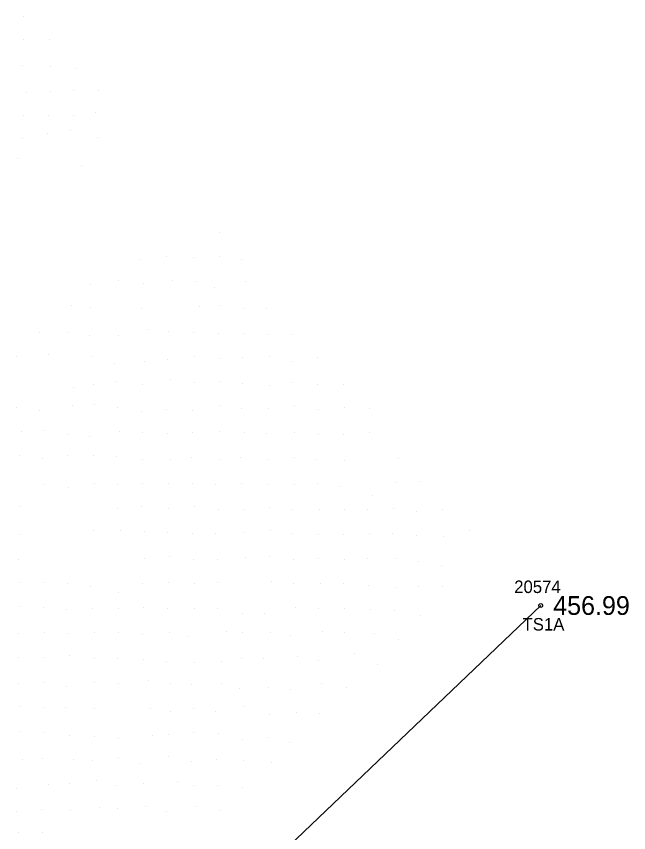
# Model space of a CAD drawing. Extents: x 1747760 to 1751131, y 649333 to 653784.
# Drawn here: x 1749292.3 to 1749341.3, y 651329.8 to 651395.1 of the extents above; entities that cross this region are included whole.
import ezdxf

# ---------------------------------------------------------------- set-up
doc = ezdxf.new("R2010")
doc.units = 0
for name, color, linetype in [('RD_DTM_BkLn2', 7, 'Continuous'), ('RD_DTM_BkLn_txCode', 7, 'Continuous'), ('RD_DTM_Spot', 7, 'Continuous'), ('RD_EX_TX_Misc_ELEV', 7, 'Continuous'), ('RD_SMD_Locator', 7, 'Continuous')]:
    doc.layers.add(name, color=color, linetype=linetype)

msp = doc.modelspace()

# ---------------------------------------------------------------- linework, layer by layer
at = {"layer": 'RD_DTM_BkLn2'}
msp.add_lwpolyline([(1749334.274, 651347.939), (1749311.737, 651326.42), (1749292.613, 651306.019), (1749271.131, 651290.935), (1749254.537, 651276.811), (1749242.73, 651265.483), (1749232.71, 651251.743), (1749211.561, 651228.743), (1749190.496, 651216.053), (1749178.766, 651203.369)], dxfattribs=at)
at = {"layer": 'RD_DTM_Spot'}
for p, q in [((1749292.882, 651395.107), (1749292.882, 651395.107)), ((1749292.871, 651393.243), (1749292.871, 651393.243)), ((1749294.951, 651393.255), (1749294.951, 651393.255)), ((1749292.804, 651391.182), (1749292.804, 651391.182)), ((1749295.066, 651391.129), (1749295.066, 651391.129)), ((1749297.111, 651390.956), (1749297.111, 651390.956)), ((1749295.032, 651389.121), (1749295.032, 651389.121)), ((1749296.894, 651389.139), (1749296.894, 651389.139)), ((1749298.853, 651389.19), (1749298.853, 651389.19)), ((1749293.146, 651389.02), (1749293.146, 651389.02)), ((1749294.871, 651387.183), (1749294.871, 651387.183)), ((1749296.905, 651387.181), (1749296.905, 651387.181)), ((1749298.636, 651387.446), (1749298.636, 651387.446)), ((1749292.929, 651387.136), (1749292.929, 651387.136)), ((1749296.614, 651385.966), (1749296.614, 651385.966)), ((1749292.834, 651385.289), (1749292.834, 651385.289)), ((1749294.792, 651385.765), (1749294.792, 651385.765)), ((1749298.822, 651385.444), (1749298.822, 651385.444)), ((1749292.409, 651383.729), (1749292.409, 651383.729)), ((1749297.559, 651383.152), (1749297.559, 651383.152)), ((1749308.556, 651377.821), (1749308.556, 651377.821)), ((1749302.269, 651375.614), (1749302.269, 651375.614)), ((1749304.349, 651375.851), (1749304.349, 651375.851)), ((1749306.491, 651375.773), (1749306.491, 651375.773)), ((1749308.577, 651375.918), (1749308.577, 651375.918)), ((1749310.36, 651375.641), (1749310.36, 651375.641)), ((1749298.265, 651373.62), (1749298.265, 651373.62)), ((1749300.482, 651373.943), (1749300.482, 651373.943)), ((1749302.484, 651373.705), (1749302.484, 651373.705)), ((1749304.836, 651373.967), (1749304.836, 651373.967)), ((1749306.685, 651373.866), (1749306.685, 651373.866)), ((1749310.682, 651373.857), (1749310.682, 651373.857)), ((1749308.135, 651373.399), (1749308.135, 651373.399)), ((1749296.695, 651371.959), (1749296.695, 651371.959)), ((1749298.221, 651371.814), (1749298.221, 651371.814)), ((1749302.3, 651371.74), (1749302.3, 651371.74)), ((1749306.954, 651371.839), (1749306.954, 651371.839)), ((1749308.684, 651371.929), (1749308.684, 651371.929)), ((1749310.533, 651371.69), (1749310.533, 651371.69)), ((1749312.349, 651371.712), (1749312.349, 651371.712)), ((1749294.175, 651369.759), (1749294.175, 651369.759)), ((1749296.531, 651369.819), (1749296.531, 651369.819)), ((1749298.199, 651369.54), (1749298.199, 651369.54)), ((1749300.531, 651369.538), (1749300.531, 651369.538)), ((1749302.887, 651370), (1749302.887, 651370)), ((1749304.53, 651369.914), (1749304.53, 651369.914)), ((1749306.509, 651369.8), (1749306.509, 651369.8)), ((1749308.491, 651369.676), (1749308.491, 651369.676)), ((1749310.613, 651369.743), (1749310.613, 651369.743)), ((1749312.447, 651369.667), (1749312.447, 651369.667)), ((1749314.344, 651369.627), (1749314.344, 651369.627)), ((1749292.357, 651367.857), (1749292.357, 651367.857)), ((1749294.865, 651368.072), (1749294.865, 651368.072)), ((1749298.312, 651367.905), (1749298.312, 651367.905)), ((1749304.437, 651367.665), (1749304.437, 651367.665)), ((1749306.601, 651367.88), (1749306.601, 651367.88)), ((1749308.597, 651367.748), (1749308.597, 651367.748)), ((1749310.394, 651367.757), (1749310.394, 651367.757)), ((1749312.568, 651367.875), (1749312.568, 651367.875)), ((1749316.383, 651367.812), (1749316.383, 651367.812)), ((1749300.178, 651367.287), (1749300.178, 651367.287)), ((1749302.541, 651367.452), (1749302.541, 651367.452)), ((1749314.421, 651367.479), (1749314.421, 651367.479)), ((1749298.524, 651365.64), (1749298.524, 651365.64)), ((1749300.362, 651365.892), (1749300.362, 651365.892)), ((1749302.419, 651365.603), (1749302.419, 651365.603)), ((1749304.641, 651366.002), (1749304.641, 651366.002)), ((1749306.544, 651365.808), (1749306.544, 651365.808)), ((1749308.562, 651365.852), (1749308.562, 651365.852)), ((1749310.432, 651365.677), (1749310.432, 651365.677)), ((1749314.428, 651365.778), (1749314.428, 651365.778)), ((1749316.398, 651365.633), (1749316.398, 651365.633)), ((1749318.517, 651365.64), (1749318.517, 651365.64)), ((1749296.915, 651365.374), (1749296.915, 651365.374)), ((1749312.546, 651365.515), (1749312.546, 651365.515)), ((1749292.335, 651363.805), (1749292.335, 651363.805)), ((1749296.806, 651363.959), (1749296.806, 651363.959)), ((1749298.558, 651364.004), (1749298.558, 651364.004)), ((1749300.374, 651363.804), (1749300.374, 651363.804)), ((1749304.318, 651363.633), (1749304.318, 651363.633)), ((1749308.637, 651363.929), (1749308.637, 651363.929)), ((1749310.33, 651363.692), (1749310.33, 651363.692)), ((1749312.482, 651363.676), (1749312.482, 651363.676)), ((1749314.578, 651363.932), (1749314.578, 651363.932)), ((1749316.479, 651363.644), (1749316.479, 651363.644)), ((1749318.555, 651363.785), (1749318.555, 651363.785)), ((1749320.609, 651363.694), (1749320.609, 651363.694)), ((1749294.14, 651363.584), (1749294.14, 651363.584)), ((1749302.361, 651363.494), (1749302.361, 651363.494)), ((1749306.403, 651363.574), (1749306.403, 651363.574)), ((1749292.727, 651361.875), (1749292.727, 651361.875)), ((1749294.546, 651361.987), (1749294.546, 651361.987)), ((1749300.55, 651361.856), (1749300.55, 651361.856)), ((1749302.422, 651361.81), (1749302.422, 651361.81)), ((1749304.425, 651361.741), (1749304.425, 651361.741)), ((1749306.379, 651361.78), (1749306.379, 651361.78)), ((1749308.548, 651361.899), (1749308.548, 651361.899)), ((1749310.535, 651361.807), (1749310.535, 651361.807)), ((1749312.371, 651361.69), (1749312.371, 651361.69)), ((1749314.536, 651361.768), (1749314.536, 651361.768)), ((1749318.494, 651361.656), (1749318.494, 651361.656)), ((1749320.574, 651361.793), (1749320.574, 651361.793)), ((1749296.449, 651361.611), (1749296.449, 651361.611)), ((1749298.201, 651361.433), (1749298.201, 651361.433)), ((1749316.493, 651361.613), (1749316.493, 651361.613)), ((1749292.551, 651359.974), (1749292.551, 651359.974)), ((1749294.402, 651359.691), (1749294.402, 651359.691)), ((1749296.444, 651359.981), (1749296.444, 651359.981)), ((1749298.475, 651359.914), (1749298.475, 651359.914)), ((1749300.343, 651359.883), (1749300.343, 651359.883)), ((1749306.36, 651359.815), (1749306.36, 651359.815)), ((1749310.268, 651359.759), (1749310.268, 651359.759)), ((1749314.537, 651359.758), (1749314.537, 651359.758)), ((1749322.936, 651359.725), (1749322.936, 651359.725)), ((1749302.382, 651359.663), (1749302.382, 651359.663)), ((1749304.642, 651359.647), (1749304.642, 651359.647)), ((1749308.562, 651359.652), (1749308.562, 651359.652)), ((1749312.435, 651359.663), (1749312.435, 651359.663)), ((1749316.293, 651359.663), (1749316.293, 651359.663)), ((1749318.554, 651359.588), (1749318.554, 651359.588)), ((1749310.361, 651357.744), (1749310.361, 651357.744)), ((1749322.694, 651357.828), (1749322.694, 651357.828)), ((1749324.605, 651357.879), (1749324.605, 651357.879)), ((1749294.529, 651357.665), (1749294.529, 651357.665)), ((1749296.502, 651357.393), (1749296.502, 651357.393)), ((1749298.556, 651357.716), (1749298.556, 651357.716)), ((1749300.402, 651357.646), (1749300.402, 651357.646)), ((1749302.386, 651357.706), (1749302.386, 651357.706)), ((1749304.494, 651357.714), (1749304.494, 651357.714)), ((1749306.396, 651357.699), (1749306.396, 651357.699)), ((1749308.289, 651357.647), (1749308.289, 651357.647)), ((1749312.419, 651357.6), (1749312.419, 651357.6)), ((1749314.601, 651357.609), (1749314.601, 651357.609)), ((1749316.422, 651357.676), (1749316.422, 651357.676)), ((1749318.284, 651357.44), (1749318.284, 651357.44)), ((1749320.782, 651356.756), (1749320.782, 651356.756)), ((1749292.555, 651355.86), (1749292.555, 651355.86)), ((1749302.358, 651355.846), (1749302.358, 651355.846)), ((1749306.539, 651355.893), (1749306.539, 651355.893)), ((1749312.592, 651355.786), (1749312.592, 651355.786)), ((1749300.395, 651355.691), (1749300.395, 651355.691)), ((1749304.51, 651355.67), (1749304.51, 651355.67)), ((1749308.462, 651355.612), (1749308.462, 651355.612)), ((1749310.507, 651355.605), (1749310.507, 651355.605)), ((1749314.455, 651355.61), (1749314.455, 651355.61)), ((1749316.596, 651355.618), (1749316.596, 651355.618)), ((1749318.552, 651355.638), (1749318.552, 651355.638)), ((1749320.413, 651355.632), (1749320.413, 651355.632)), ((1749322.497, 651355.693), (1749322.497, 651355.693)), ((1749324.353, 651355.5), (1749324.353, 651355.5)), ((1749326.444, 651355.636), (1749326.444, 651355.636)), ((1749298.515, 651353.955), (1749298.515, 651353.955)), ((1749300.629, 651353.913), (1749300.629, 651353.913)), ((1749302.539, 651353.826), (1749302.539, 651353.826)), ((1749312.69, 651353.937), (1749312.69, 651353.937)), ((1749328.554, 651353.953), (1749328.554, 651353.953)), ((1749292.626, 651353.604), (1749292.626, 651353.604)), ((1749304.428, 651353.759), (1749304.428, 651353.759)), ((1749306.432, 651353.675), (1749306.432, 651353.675)), ((1749308.251, 651353.728), (1749308.251, 651353.728)), ((1749310.591, 651353.788), (1749310.591, 651353.788)), ((1749314.422, 651353.706), (1749314.422, 651353.706)), ((1749316.483, 651353.6), (1749316.483, 651353.6)), ((1749318.465, 651353.603), (1749318.465, 651353.603)), ((1749320.575, 651353.71), (1749320.575, 651353.71)), ((1749322.446, 651353.707), (1749322.446, 651353.707)), ((1749324.366, 651353.535), (1749324.366, 651353.535)), ((1749326.506, 651353.491), (1749326.506, 651353.491)), ((1749304.554, 651351.886), (1749304.554, 651351.886)), ((1749292.509, 651351.601), (1749292.509, 651351.601)), ((1749302.539, 651351.698), (1749302.539, 651351.698)), ((1749306.472, 651351.659), (1749306.472, 651351.659)), ((1749308.452, 651351.601), (1749308.452, 651351.601)), ((1749310.657, 651351.823), (1749310.657, 651351.823)), ((1749312.568, 651351.845), (1749312.568, 651351.845)), ((1749314.472, 651351.594), (1749314.472, 651351.594)), ((1749316.524, 651351.698), (1749316.524, 651351.698)), ((1749318.6, 651351.636), (1749318.6, 651351.636)), ((1749320.441, 651351.728), (1749320.441, 651351.728)), ((1749322.738, 651351.728), (1749322.738, 651351.728)), ((1749324.459, 651351.456), (1749324.459, 651351.456)), ((1749326.36, 651351.18), (1749326.36, 651351.18)), ((1749292.636, 651349.807), (1749292.636, 651349.807)), ((1749294.453, 651349.798), (1749294.453, 651349.798)), ((1749296.379, 651349.73), (1749296.379, 651349.73)), ((1749298.288, 651349.484), (1749298.288, 651349.484)), ((1749302.436, 651349.694), (1749302.436, 651349.694)), ((1749304.455, 651349.746), (1749304.455, 651349.746)), ((1749306.565, 651349.734), (1749306.565, 651349.734)), ((1749308.442, 651349.758), (1749308.442, 651349.758)), ((1749312.716, 651349.826), (1749312.716, 651349.826)), ((1749314.513, 651349.738), (1749314.513, 651349.738)), ((1749316.635, 651349.664), (1749316.635, 651349.664)), ((1749318.501, 651349.73), (1749318.501, 651349.73)), ((1749320.523, 651349.509), (1749320.523, 651349.509)), ((1749322.743, 651349.416), (1749322.743, 651349.416)), ((1749324.518, 651349.457), (1749324.518, 651349.457)), ((1749326.383, 651349.443), (1749326.383, 651349.443)), ((1749300.504, 651348.985), (1749300.504, 651348.985)), ((1749292.657, 651347.823), (1749292.657, 651347.823)), ((1749294.471, 651347.748), (1749294.471, 651347.748)), ((1749296.37, 651347.622), (1749296.37, 651347.622)), ((1749298.45, 651347.673), (1749298.45, 651347.673)), ((1749300.518, 651347.698), (1749300.518, 651347.698)), ((1749302.462, 651347.752), (1749302.462, 651347.752)), ((1749304.383, 651347.686), (1749304.383, 651347.686)), ((1749306.538, 651347.71), (1749306.538, 651347.71)), ((1749308.45, 651347.685), (1749308.45, 651347.685)), ((1749310.426, 651347.312), (1749310.426, 651347.312)), ((1749312.18, 651347.314), (1749312.18, 651347.314)), ((1749314.632, 651347.779), (1749314.632, 651347.779)), ((1749316.501, 651347.69), (1749316.501, 651347.69)), ((1749318.549, 651347.677), (1749318.549, 651347.677)), ((1749320.618, 651347.608), (1749320.618, 651347.608)), ((1749322.584, 651347.529), (1749322.584, 651347.529)), ((1749324.654, 651347.137), (1749324.654, 651347.137)), ((1749292.492, 651345.69), (1749292.492, 651345.69)), ((1749294.565, 651345.799), (1749294.565, 651345.799)), ((1749296.485, 651345.667), (1749296.485, 651345.667)), ((1749298.543, 651345.787), (1749298.543, 651345.787)), ((1749300.454, 651345.799), (1749300.454, 651345.799)), ((1749302.449, 651345.59), (1749302.449, 651345.59)), ((1749304.609, 651345.744), (1749304.609, 651345.744)), ((1749306.058, 651345.477), (1749306.058, 651345.477)), ((1749309.12, 651345.844), (1749309.12, 651345.844)), ((1749310.437, 651345.746), (1749310.437, 651345.746)), ((1749312.632, 651345.744), (1749312.632, 651345.744)), ((1749314.282, 651345.552), (1749314.282, 651345.552)), ((1749316.817, 651345.856), (1749316.817, 651345.856)), ((1749318.557, 651345.757), (1749318.557, 651345.757)), ((1749320.947, 651345.698), (1749320.947, 651345.698)), ((1749322.929, 651345.223), (1749322.929, 651345.223)), ((1749319.366, 651344.077), (1749319.366, 651344.077)), ((1749292.525, 651343.767), (1749292.525, 651343.767)), ((1749294.491, 651343.758), (1749294.491, 651343.758)), ((1749296.541, 651343.928), (1749296.541, 651343.928)), ((1749298.544, 651343.735), (1749298.544, 651343.735)), ((1749300.452, 651343.697), (1749300.452, 651343.697)), ((1749302.523, 651343.621), (1749302.523, 651343.621)), ((1749304.363, 651343.479), (1749304.363, 651343.479)), ((1749306.562, 651343.355), (1749306.562, 651343.355)), ((1749308.737, 651343.488), (1749308.737, 651343.488)), ((1749310.367, 651343.678), (1749310.367, 651343.678)), ((1749312.133, 651343.732), (1749312.133, 651343.732)), ((1749314.847, 651343.828), (1749314.847, 651343.828)), ((1749316.514, 651343.519), (1749316.514, 651343.519)), ((1749321.224, 651343.23), (1749321.224, 651343.23)), ((1749292.47, 651341.708), (1749292.47, 651341.708)), ((1749294.475, 651341.795), (1749294.475, 651341.795)), ((1749296.358, 651341.446), (1749296.358, 651341.446)), ((1749298.582, 651341.75), (1749298.582, 651341.75)), ((1749300.497, 651341.685), (1749300.497, 651341.685)), ((1749302.877, 651341.923), (1749302.877, 651341.923)), ((1749304.677, 651341.67), (1749304.677, 651341.67)), ((1749306.354, 651341.637), (1749306.354, 651341.637)), ((1749308.756, 651341.708), (1749308.756, 651341.708)), ((1749312.474, 651341.397), (1749312.474, 651341.397)), ((1749316.698, 651341.716), (1749316.698, 651341.716)), ((1749318.702, 651341.412), (1749318.702, 651341.412)), ((1749310.191, 651341.258), (1749310.191, 651341.258)), ((1749314.224, 651341.177), (1749314.224, 651341.177)), ((1749292.543, 651339.882), (1749292.543, 651339.882)), ((1749294.498, 651339.789), (1749294.498, 651339.789)), ((1749296.254, 651339.809), (1749296.254, 651339.809)), ((1749298.608, 651339.675), (1749298.608, 651339.675)), ((1749303.074, 651339.732), (1749303.074, 651339.732)), ((1749306.46, 651339.706), (1749306.46, 651339.706)), ((1749308.27, 651339.457), (1749308.27, 651339.457)), ((1749310.59, 651339.825), (1749310.59, 651339.825)), ((1749304.671, 651339.421), (1749304.671, 651339.421)), ((1749312.544, 651339.214), (1749312.544, 651339.214)), ((1749314.731, 651339.395), (1749314.731, 651339.395)), ((1749316.561, 651339.275), (1749316.561, 651339.275)), ((1749292.593, 651337.859), (1749292.593, 651337.859)), ((1749294.502, 651337.774), (1749294.502, 651337.774)), ((1749296.546, 651337.548), (1749296.546, 651337.548)), ((1749303.229, 651337.565), (1749303.229, 651337.565)), ((1749304.458, 651337.618), (1749304.458, 651337.618)), ((1749306.52, 651337.806), (1749306.52, 651337.806)), ((1749308.533, 651337.679), (1749308.533, 651337.679)), ((1749298.588, 651337.453), (1749298.588, 651337.453)), ((1749300.52, 651337.316), (1749300.52, 651337.316)), ((1749310.375, 651337.244), (1749310.375, 651337.244)), ((1749312.5, 651337.38), (1749312.5, 651337.38)), ((1749314.173, 651336.945), (1749314.173, 651336.945)), ((1749292.806, 651335.604), (1749292.806, 651335.604)), ((1749294.419, 651335.68), (1749294.419, 651335.68)), ((1749296.915, 651335.633), (1749296.915, 651335.633)), ((1749298.392, 651335.54), (1749298.392, 651335.54)), ((1749300.501, 651335.782), (1749300.501, 651335.782)), ((1749304.51, 651335.853), (1749304.51, 651335.853)), ((1749308.36, 651335.593), (1749308.36, 651335.593)), ((1749310.461, 651335.534), (1749310.461, 651335.534)), ((1749302.254, 651335.314), (1749302.254, 651335.314)), ((1749306.368, 651335.482), (1749306.368, 651335.482)), ((1749312.725, 651335.351), (1749312.725, 651335.351)), ((1749294.91, 651333.585), (1749294.91, 651333.585)), ((1749296.541, 651333.722), (1749296.541, 651333.722)), ((1749298.748, 651333.924), (1749298.748, 651333.924)), ((1749302.512, 651333.661), (1749302.512, 651333.661)), ((1749305.205, 651333.834), (1749305.205, 651333.834)), ((1749292.331, 651333.327), (1749292.331, 651333.327)), ((1749300.219, 651333.531), (1749300.219, 651333.531)), ((1749306.475, 651333.535), (1749306.475, 651333.535)), ((1749308.4, 651333.537), (1749308.4, 651333.537)), ((1749310.384, 651333.347), (1749310.384, 651333.347)), ((1749294.308, 651331.632), (1749294.308, 651331.632)), ((1749298.936, 651331.809), (1749298.936, 651331.809)), ((1749300.385, 651331.705), (1749300.385, 651331.705)), ((1749302.628, 651331.871), (1749302.628, 651331.871)), ((1749306.71, 651331.835), (1749306.71, 651331.835)), ((1749292.341, 651331.472), (1749292.341, 651331.472)), ((1749296.639, 651331.552), (1749296.639, 651331.552)), ((1749304.372, 651331.474), (1749304.372, 651331.474)), ((1749308.589, 651331.502), (1749308.589, 651331.502)), ((1749292.489, 651329.769), (1749292.489, 651329.769)), ((1749294.435, 651329.77), (1749294.435, 651329.77))]:
    msp.add_line(p, q, dxfattribs=at)
at = {"layer": 'RD_SMD_Locator'}
msp.add_circle((1749334.274, 651347.939), 0.15, dxfattribs=at)

# ---------------------------------------------------------------- texts
at = {"layer": 'RD_DTM_BkLn_txCode'}
for s, p in [('20574', (1749332.156, 651348.939)), ('TS1A', (1749332.825, 651345.939))]:
    msp.add_text(s, height=1, dxfattribs=at).set_placement(p)
at = {"layer": 'RD_EX_TX_Misc_ELEV'}
msp.add_text('456.99', height=1.5, dxfattribs=at).set_placement((1749335.274, 651347.189))

doc.saveas('drawing.dxf')
